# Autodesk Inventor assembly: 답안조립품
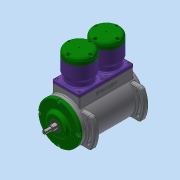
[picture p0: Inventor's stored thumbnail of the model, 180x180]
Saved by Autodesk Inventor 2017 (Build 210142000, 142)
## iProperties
Part Number: 답안조립품
Material: 일반
Document SubType Name: Assembly
Designer: Administrator
Mass: 7371.37 g
Surface Area: 5215.2 cm^2
Volume: 2062.19 cm^3
Density: 3.57453 g/cm^3
Author: Administrator
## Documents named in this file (16)
- C:\Users\Administrator\Desktop\620106V1011\답안조립품.iam
- C:\Users\Administrator\Desktop\620106V1011\본체.ipt
- C:\Users\Administrator\Desktop\620106V1011\크랭크축.ipt
- C:\Users\Administrator\Desktop\620106V1011\베어링 6303.ipt
- C:\Users\Administrator\Desktop\620106V1011\앞커버.ipt
- C:\Users\Administrator\Desktop\620106V1011\오일 실 17 x 32 x 8.ipt
- C:\Users\Administrator\Desktop\620106V1011\볼트 M4 x 12.ipt
- C:\Users\Administrator\Desktop\620106V1011\실린더.ipt
- C:\Users\Administrator\Desktop\620106V1011\실린더헤드.ipt
- C:\Users\Administrator\Desktop\620106V1011\볼트 M5 x 20.ipt
- C:\Users\Administrator\Desktop\620106V1011\커넥팅로드.ipt
- C:\Users\Administrator\Desktop\620106V1011\커넥팅로드 엔드.ipt
- C:\Users\Administrator\Desktop\620106V1011\육각 머리 볼트 M4 x 16.ipt
- C:\Users\Administrator\Desktop\620106V1011\너트 M4.ipt
- C:\Users\Administrator\Desktop\620106V1011\피스톤.ipt
- C:\Users\Administrator\Desktop\620106V1011\피스톤핀.ipt
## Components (4 placed, 2 different names)
1. 피스톤:1
2. 피스톤핀:1
3. 피스톤:2
4. 피스톤핀:2
